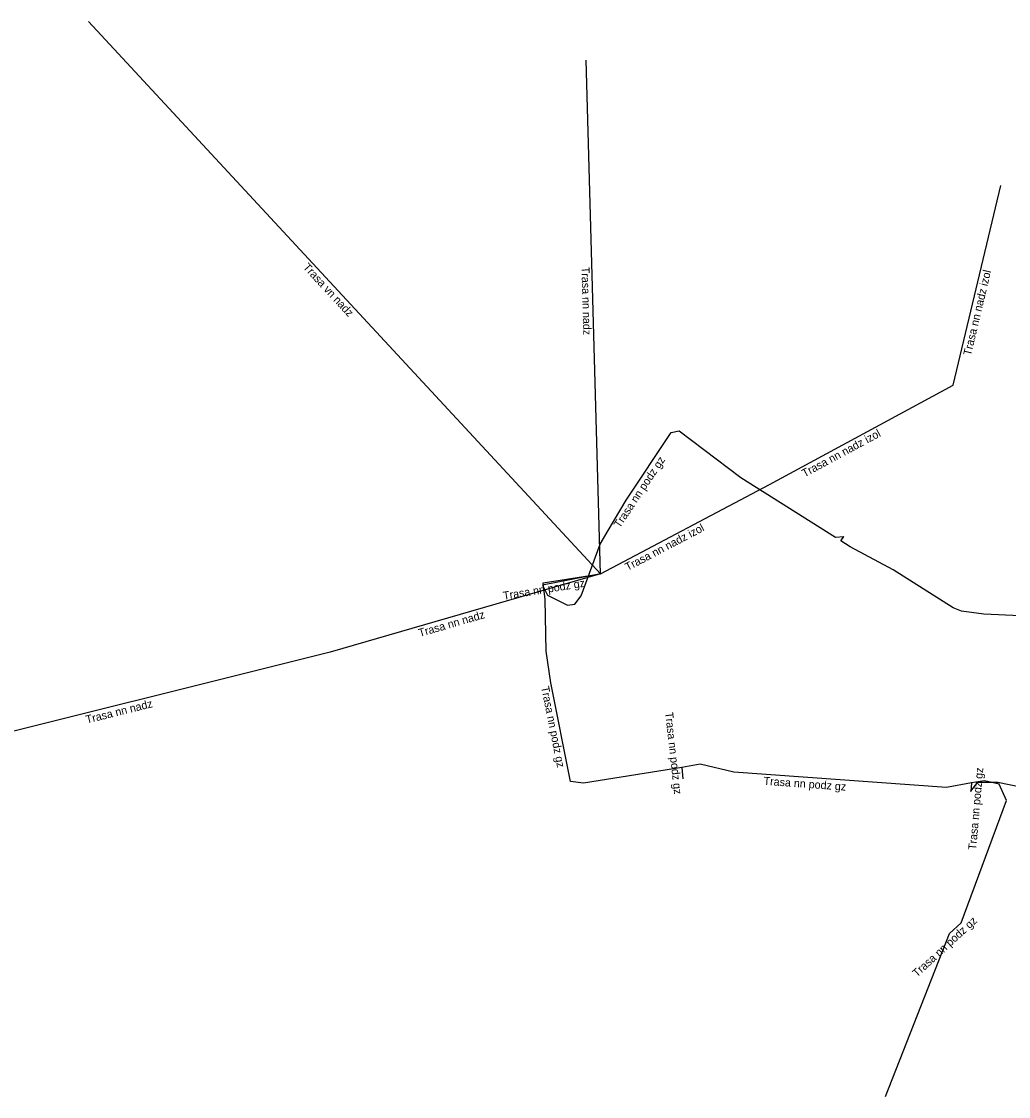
# Model space of a CAD drawing. Extents: x -771127 to -770600, y -1049993 to -1049871.
# Drawn here: x -770975.4 to -770913.8, y -1049938.2 to -1049871.1 of the extents above; entities that cross this region are included whole.
import ezdxf

# ---------------------------------------------------------------- set-up
doc = ezdxf.new("R2010")
doc.units = 0
for name, color, linetype in [('Popiskový text - Ostatní atributy Trasy', 7, 'Continuous'), ('Spojnice NN', 7, 'Continuous'), ('Spojnice VN', 7, 'Continuous')]:
    doc.layers.add(name, color=color, linetype=linetype)

msp = doc.modelspace()

# ---------------------------------------------------------------- linework, layer by layer
at = {"layer": 'Spojnice NN'}
for points in [[(-770939.278, -1049905.536), (-770940.167, -1049873.471)], [(-770917.242, -1049893.764), (-770914.27, -1049881.295)], [(-770928.716, -1049899.971), (-770917.242, -1049893.764)], [(-770939.278, -1049905.536), (-770942.9, -1049906.26), (-770942.58, -1049906.88), (-770941.34, -1049907.49), (-770940.88, -1049907.44), (-770940.47, -1049906.92), (-770939.29, -1049903.68), (-770938.8, -1049902.84), (-770937.67, -1049900.95), (-770934.85, -1049896.71), (-770934.36, -1049896.62), (-770930.5, -1049899.53), (-770924.59, -1049903.26), (-770924.086, -1049903.205)], [(-770939.278, -1049905.536), (-770928.716, -1049899.971)], [(-770894.77, -1049908.46), (-770895.72, -1049908.36), (-770901.53, -1049907.14), (-770904.97, -1049906.4), (-770906.15, -1049906.76), (-770910.13, -1049908.14), (-770911.26, -1049908.24), (-770915.34, -1049908.06), (-770916.73, -1049907.87), (-770917.24, -1049907.66), (-770921, -1049905.3), (-770923.68, -1049903.85), (-770924.27, -1049903.49), (-770924.086, -1049903.205)], [(-770939.278, -1049905.536), (-770956.149, -1049910.434)], [(-770942.735, -1049907.139), (-770942.84, -1049906.109), (-770939.278, -1049905.536)], [(-770934.199, -1049917.641), (-770940.326, -1049918.604), (-770941.136, -1049918.498), (-770942.374, -1049912.338), (-770942.671, -1049910.366), (-770942.735, -1049907.139)], [(-770956.149, -1049910.434), (-770980.74, -1049916.57)], [(-770916.098, -1049918.592), (-770917.667, -1049918.882), (-770930.947, -1049917.924), (-770933.039, -1049917.434), (-770934.199, -1049917.641)], [(-770934.199, -1049917.641), (-770934.12, -1049918.348)], [(-770921.479, -1049938.173), (-770917.473, -1049927.991), (-770916.745, -1049927.321), (-770913.923, -1049919.692), (-770914.377, -1049918.677), (-770915.288, -1049918.474), (-770916.098, -1049918.592)], [(-770916.146, -1049919.137), (-770916.149, -1049919.119), (-770915.71, -1049918.54), (-770914.47, -1049918.54), (-770910.01, -1049919.47), (-770906.04, -1049920.76), (-770903.65, -1049921.31), (-770895.3, -1049923.25), (-770889.11, -1049924.61), (-770888.24, -1049924.81)], [(-770916.098, -1049918.592), (-770916.146, -1049919.137)]]:
    msp.add_lwpolyline(points, dxfattribs=at)
at = {"layer": 'Spojnice VN'}
msp.add_lwpolyline([(-770971.243, -1049871.059), (-770939.278, -1049905.536)], dxfattribs=at)

# ---------------------------------------------------------------- texts
at = {"layer": 'Popiskový text - Ostatní atributy Trasy'}
for s, rotation, p in [('Trasa vn nadz', 312.83483, (-770957.877, -1049886.431)), ('Trasa nn nadz', 271.58811, (-770940.459, -1049886.375)), ('Trasa nn nadz izol', 76.59363, (-770916.142, -1049891.95)), ('Trasa nn nadz izol', 28.41179, (-770926.53, -1049899.528)), ('Trasa nn podz gz', 56.37235, (-770938.067, -1049902.721)), ('Trasa nn nadz izol', 27.78419, (-770937.577, -1049905.374)), ('Trasa nn podz gz', 9.13858, (-770945.312, -1049907.165)), ('Trasa nn nadz', 16.18911, (-770950.555, -1049909.487)), ('Trasa nn podz gz', 281.36358, (-770942.982, -1049912.61)), ('Trasa nn nadz', 14.01047, (-770971.341, -1049914.895)), ('Trasa nn podz gz', 276.37577, (-770935.238, -1049914.197)), ('Trasa nn podz gz', 84.96675, (-770915.817, -1049922.801)), ('Trasa nn podz gz', 355.87391, (-770929.101, -1049918.709)), ('Trasa nn podz gz', 42.62428, (-770919.513, -1049930.752))]:
    msp.add_text(s, height=0.5, rotation=rotation, dxfattribs=at).set_placement(p)

doc.saveas('drawing.dxf')
